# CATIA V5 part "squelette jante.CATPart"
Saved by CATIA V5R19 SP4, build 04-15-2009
Part number: squelette jante
Bounding box of the stored display mesh (mm): x 400 to 1100, y 0 to 353.553, z 0 to 353.553
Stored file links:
  G:\EU_thinkMotion\CFAO_2010\MMS_groupe1\MMS_groupe1\OK\rragonneau\rragonneau\squelette jante.CATPart
  G:\EU_thinkMotion\CFAO_2010\MMS_groupe1\MMS_groupe1\OK\rragonneau\rragonneau\Squelette.CATProduct
  G:\EU_thinkMotion\CFAO_2010\MMS_groupe1\MMS_groupe1\OK\rragonneau\rragonneau\squelette bras 1.CATPart
  G:\EU_thinkMotion\CFAO_2010\MMS_groupe1\MMS_groupe1\OK\rragonneau\rragonneau\squelette de base.CATPart
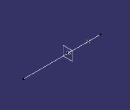
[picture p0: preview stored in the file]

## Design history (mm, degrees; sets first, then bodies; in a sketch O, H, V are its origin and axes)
Set1
  Line1: type PtPt, FirstPoint DatumPoint1, SecondPoint DatumPoint2, End 500
  Point1: type OnPlane, Support Plane1, H 0, V 0, Direction (0, 1, 0)
  Line2: type PtDir, RefPoint Point1, Direction (0, 1, 1), Start 0, End 500
Set2
  DatumPoint1: linked copy from another document
  DatumPoint2: linked copy from another document
  Plane1: linked copy from another document
Body1 (main body)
